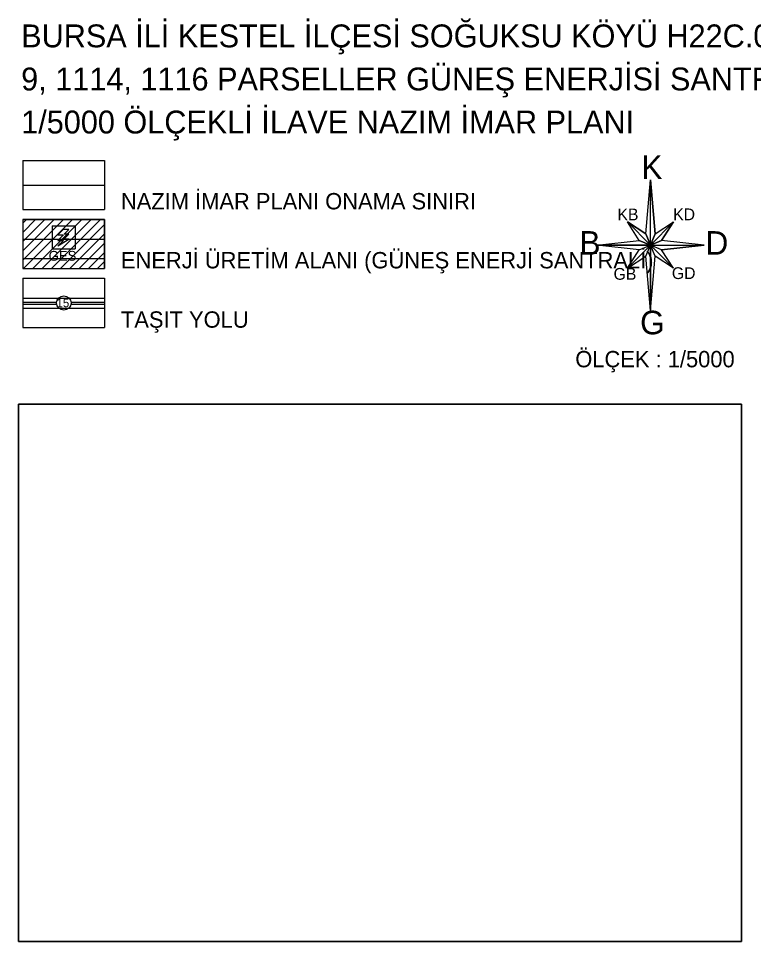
# Model space of a CAD drawing. Extents: x 449035 to 450868, y 4452351 to 4453762.
# Drawn here: x 449035 to 450158, y 4452351 to 4453762 of the extents above; entities that cross this region are included whole.
import ezdxf

# ---------------------------------------------------------------- set-up
doc = ezdxf.new("R2010")
doc.units = 0
for name, color, linetype in [('1', 7, 'Continuous'), ('ADAKENARI', 7, 'Continuous'), ('KALDIRIM', 7, 'Continuous'), ('KD_DAIRE', 7, 'Continuous'), ('KD_YGEN', 7, 'Continuous'), ('LEJAND', 7, 'Continuous'), ('PL_ENERJI_URETIM_ALANI', 7, 'Continuous'), ('SN_ONAY', 7, 'Continuous'), ('TR_ENERJİSANTRALİ', 7, 'Continuous')]:
    doc.layers.add(name, color=color, linetype=linetype)

msp = doc.modelspace()

# ---------------------------------------------------------------- linework, layer by layer
at = {"layer": '1'}
msp.add_lwpolyline([(449034.9, 4452350.8), (450139.4, 4452350.8), (450139.4, 4453172.3), (449034.9, 4453172.3)], close=True, dxfattribs=at)
at = {"layer": 'ADAKENARI'}
for p, q in [((449041.4, 4453334.2), (449166.4, 4453334.2)), ((449041.4, 4453319.2), (449166.4, 4453319.2))]:
    msp.add_line(p, q, dxfattribs=at)
at = {"layer": 'KALDIRIM'}
for p, q in [((449041.4, 4453328.2), (449093.3, 4453328.2)), ((449115.2, 4453328.2), (449166.4, 4453328.2)), ((449041.4, 4453325.2), (449093.4, 4453325.2)), ((449115.1, 4453325.2), (449166.4, 4453325.2))]:
    msp.add_line(p, q, dxfattribs=at)
at = {"layer": 'KD_DAIRE'}
msp.add_circle((449104.2, 4453327), 11, dxfattribs=at)
at = {"layer": 'LEJAND'}
for p, q in [((449041.4, 4453544.7), (449166.4, 4453544.7)), ((449041.4, 4453544.7), (449041.4, 4453469.7)), ((449166.4, 4453544.7), (449166.4, 4453469.7)), ((449993.3, 4453432.6), (450000.4, 4453515.5)), ((450007.4, 4453432.6), (450000.4, 4453515.5)), ((449041.4, 4453469.7), (449166.4, 4453469.7)), ((449041.4, 4453454.7), (449166.4, 4453454.7)), ((449041.4, 4453454.7), (449041.4, 4453379.7)), ((449166.4, 4453454.7), (449166.4, 4453379.7)), ((449086.4, 4453445), (449121.4, 4453445)), ((449086.4, 4453445), (449086.4, 4453410)), ((449103.2, 4453439.2), (449095.2, 4453431.2)), ((449111.7, 4453439.2), (449103.2, 4453439.2)), ((449104.7, 4453432.2), (449111.7, 4453439.2)), ((449121.4, 4453445), (449121.4, 4453410)), ((450000.4, 4453415.6), (449965.1, 4453450.9)), ((449993.3, 4453432.6), (449965.1, 4453450.9)), ((449983.3, 4453422.7), (449965.1, 4453450.9)), ((450000.4, 4453415.6), (450035.7, 4453450.9)), ((450007.4, 4453432.6), (450035.7, 4453450.9)), ((450017.4, 4453422.6), (450035.7, 4453450.9)), ((449095.2, 4453431.2), (449103.7, 4453431.2)), ((449103.7, 4453431.2), (449095.2, 4453422.7)), ((449095.2, 4453414.2), (449111.7, 4453424.7)), ((449104.2, 4453424.7), (449111.7, 4453432.2)), ((449111.7, 4453424.7), (449104.2, 4453424.7)), ((449111.7, 4453432.2), (449104.7, 4453432.2)), ((450000.4, 4453415.6), (449993.3, 4453432.6)), ((450000.4, 4453415.6), (450007.4, 4453432.6)), ((449095.2, 4453422.7), (449103.7, 4453422.7)), ((449103.7, 4453422.7), (449095.2, 4453414.2)), ((449918.4, 4453415.6), (449983.3, 4453422.7)), ((449918.4, 4453415.6), (450000.4, 4453415.6)), ((449983.3, 4453408.5), (449918.4, 4453415.6)), ((449965.1, 4453380.3), (450000.4, 4453415.6)), ((450000.4, 4453415.6), (449983.3, 4453422.7)), ((449983.3, 4453408.5), (450000.4, 4453415.6)), ((449993.3, 4453398.5), (450000.4, 4453415.6)), ((450000.4, 4453415.6), (450017.4, 4453422.6)), ((450000.4, 4453415.6), (450082.4, 4453415.6)), ((450000.4, 4453315.7), (450000.4, 4453415.6)), ((450035.7, 4453380.3), (450000.4, 4453415.6)), ((450017.4, 4453408.5), (450000.4, 4453415.6)), ((450007.4, 4453398.5), (450000.4, 4453415.6)), ((450082.4, 4453415.6), (450017.4, 4453422.6)), ((450017.4, 4453408.5), (450082.4, 4453415.6)), ((449086.4, 4453410), (449121.4, 4453410)), ((449965.1, 4453380.3), (449983.3, 4453408.5)), ((449965.1, 4453380.3), (449993.3, 4453398.5)), ((450000.4, 4453315.7), (449993.3, 4453398.5)), ((450000.4, 4453315.7), (450007.4, 4453398.5)), ((450035.7, 4453380.3), (450007.4, 4453398.5)), ((450035.7, 4453380.3), (450017.4, 4453408.5)), ((449041.4, 4453379.7), (449166.4, 4453379.7)), ((449041.4, 4453364.7), (449166.4, 4453364.7)), ((449041.4, 4453364.7), (449041.4, 4453289.7)), ((449166.4, 4453364.7), (449166.4, 4453289.7)), ((449041.4, 4453289.7), (449166.4, 4453289.7)), ((449034.9, 4452350.8), (449034.9, 4453172.3)), ((449034.9, 4453172.3), (450139.4, 4453172.3)), ((450139.4, 4453172.3), (450139.4, 4452350.8)), ((450139.4, 4452350.8), (449034.9, 4452350.8))]:
    msp.add_line(p, q, dxfattribs=at)
for points in [[(450000.4, 4453515.5), (450007.4, 4453432.6), (450000.4, 4453415.6)], [(449965.1, 4453450.9), (449993.3, 4453432.6), (450000.4, 4453415.6)], [(450035.7, 4453450.9), (450017.4, 4453422.6), (450000.4, 4453415.6)], [(449983.3, 4453422.7), (450000.4, 4453415.6), (449918.4, 4453415.6)], [(450000.4, 4453415.6), (449965.1, 4453380.3), (449983.3, 4453408.5)], [(450000.4, 4453415.6), (450000.4, 4453315.7), (449993.3, 4453398.5)], [(450000.4, 4453415.6), (450082.4, 4453415.6), (450017.4, 4453408.5)], [(450000.4, 4453415.6), (450035.7, 4453380.3), (450007.4, 4453398.5)]]:
    msp.add_lwpolyline(points, close=True, dxfattribs=at)
at = {"layer": 'PL_ENERJI_URETIM_ALANI'}
msp.add_lwpolyline([(449041.4, 4453454.7), (449041.4, 4453379.7), (449166.4, 4453379.7), (449166.4, 4453454.7)], close=True, dxfattribs=at)
at = {"layer": 'SN_ONAY'}
msp.add_line((449041.4, 4453507.2), (449166.4, 4453507.2), dxfattribs=at)
at = {"layer": 'TR_ENERJİSANTRALİ'}
for p, q in [((449041.4, 4453392.6), (449103.5, 4453454.7)), ((449041.4, 4453406.7), (449089.3, 4453454.7)), ((449041.4, 4453420.8), (449075.2, 4453454.7)), ((449041.4, 4453435), (449061.1, 4453454.7)), ((449041.4, 4453449.1), (449046.9, 4453454.7)), ((449042.6, 4453379.7), (449117.6, 4453454.7)), ((449056.8, 4453379.7), (449131.8, 4453454.7)), ((449070.9, 4453379.7), (449145.9, 4453454.7)), ((449085.1, 4453379.7), (449160.1, 4453454.7)), ((449099.2, 4453379.7), (449166.4, 4453446.9)), ((449041.4, 4453424.8), (449166.4, 4453424.8)), ((449113.3, 4453379.7), (449166.4, 4453432.7)), ((449127.5, 4453379.7), (449166.4, 4453418.6)), ((449141.6, 4453379.7), (449166.4, 4453404.4)), ((449041.4, 4453394.8), (449166.4, 4453394.8)), ((449155.8, 4453379.7), (449166.4, 4453390.3))]:
    msp.add_line(p, q, dxfattribs=at)

# ---------------------------------------------------------------- texts
at = {"layer": 'KD_YGEN'}
msp.add_text('15', height=13, dxfattribs=at).set_placement((449093.1, 4453320.6))
at = {"layer": 'LEJAND'}
for s, height, p in [('BURSA İLİ KESTEL İLÇESİ SOĞUKSU KÖYÜ H22C.04D PAFTA ', 35, (449039, 4453717.8)), ('9, 1114, 1116 PARSELLER GÜNEŞ ENERJİSİ SANTRALİ AMAÇLI', 35, (449039, 4453651.9)), ('1/5000 ÖLÇEKLİ İLAVE NAZIM İMAR PLANI', 35, (449039, 4453586.1)), ('NAZIM İMAR PLANI ONAMA SINIRI', 25, (449191.4, 4453470.1)), ('ENERJİ ÜRETİM ALANI (GÜNEŞ ENERJİ SANTRALİ)', 25, (449191.4, 4453379.9)), ('GES', 15, (449081, 4453391.6)), ('TAŞIT YOLU', 25, (449191.4, 4453289.2))]:
    msp.add_text(s, height=height, dxfattribs=at).set_placement(p)
for s, height, p in [('K', 36, (449986.4, 4453516.6)), ('KB', 18, (449949.9, 4453453.4)), ('KD', 18, (450035, 4453453.5)), ('B', 36, (449891.9, 4453400.9)), ('D', 36, (450084.5, 4453400.8)), ('GB', 18, (449944, 4453362.5)), ('GD', 18, (450033, 4453363.6)), ('G', 36, (449984.5, 4453279.1)), ('ÖLÇEK : 1/5000', 25, (449885.5, 4453228.7))]:
    msp.add_text(s, height=height, rotation=359.9901, dxfattribs=at).set_placement(p)

doc.saveas('drawing.dxf')
